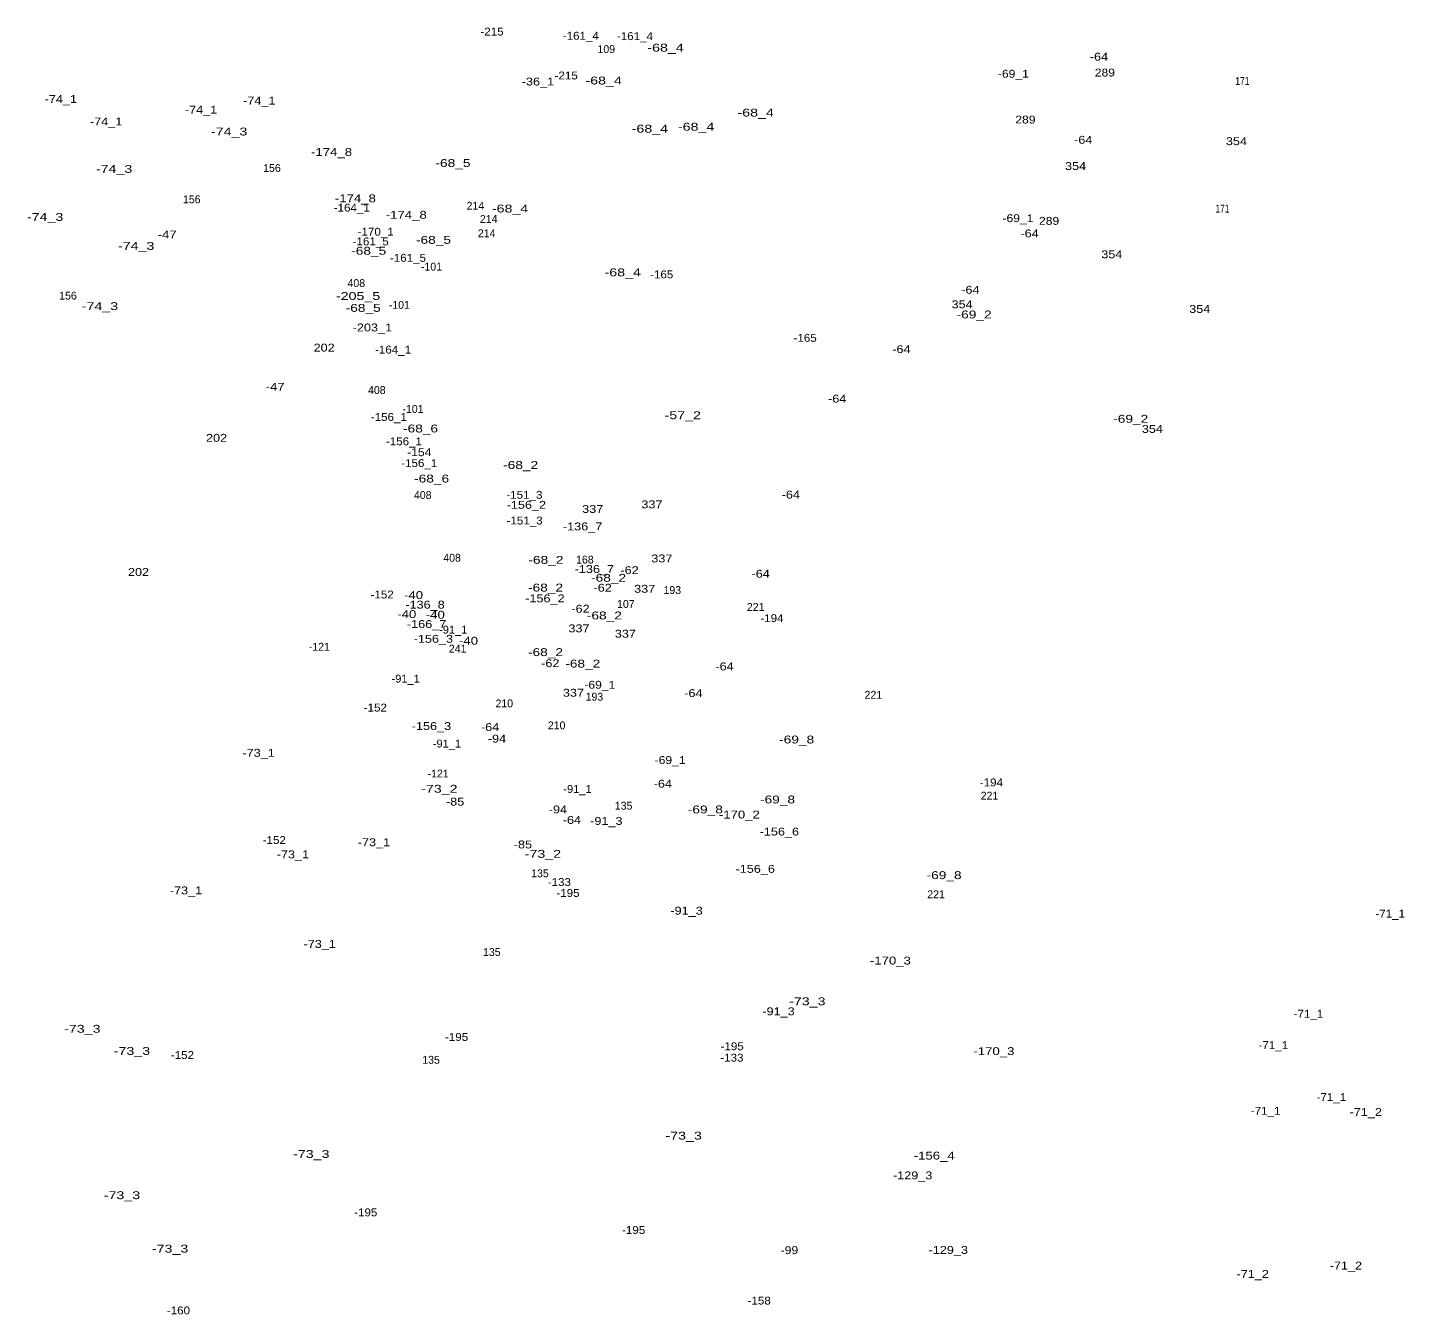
# Model space of a CAD drawing. Extents: x -658110 to -655750, y -1000429 to -997657.
# Drawn here: x -657635 to -656936, y -999768 to -999114 of the extents above; entities that cross this region are included whole.
import ezdxf
from ezdxf.enums import TextEntityAlignment as Align

# ---------------------------------------------------------------- set-up
doc = ezdxf.new("R2010")
doc.units = 0
doc.header["$LTSCALE"] = 1.6
doc.layers.add('24', color=7, linetype='Continuous')

msp = doc.modelspace()

# ---------------------------------------------------------------- texts
at = {"layer": '24'}
for s, width, p in [('-215', 1.1, (-657399.14, -999118.46)), ('-161_4', 1.1, (-657354.09, -999120.58)), ('-161_4', 1.1, (-657326.63, -999120.77)), ('-68_4', 1.35, (-657311.09, -999126.62)), ('-64', 1.2, (-657091.14, -999131.19)), ('-36_1', 1.2, (-657375.841, -999143.81)), ('-215', 1.1, (-657361.51, -999140.74)), ('-68_4', 1.35, (-657342.5, -999143.3)), ('-69_1', 1.15, (-657134.58, -999139.85)), ('289', 1.15, (-657088.14, -999139.25)), ('171', 0.8, (-657018.361, -999143.51)), ('-74_1', 1.2, (-657617.99, -999152.69)), ('-74_1', 1.2, (-657546.81, -999158.11)), ('-74_1', 1.2, (-657517.22, -999153.46)), ('-74_1', 1.2, (-657594.97, -999164.1)), ('-68_4', 1.35, (-657265.34, -999159.59)), ('289', 1.15, (-657128.46, -999163.1)), ('-74_3', 1.35, (-657532.54, -999169.18)), ('-68_4', 1.35, (-657319.04, -999167.73)), ('-68_4', 1.35, (-657295.58, -999166.76)), ('-174_8', 1.25, (-657480.59, -999179.55)), ('-64', 1.2, (-657099.111, -999173.38)), ('354', 1.2, (-657021.38, -999174.08)), ('-68_5', 1.3, (-657418.97, -999185.17)), ('354', 1.2, (-657103, -999186.68)), ('-74_3', 1.35, (-657590.949, -999188.14)), ('-174_8', 1.25, (-657468.49, -999203.08)), ('-74_3', 1.35, (-657625.949, -999212.52)), ('-164_1', 1.1, (-657470.32, -999207.82)), ('-174_8', 1.25, (-657442.67, -999211.44)), ('-68_4', 1.35, (-657389.99, -999208.26)), ('-69_1', 1.15, (-657132.25, -999213.16)), ('289', 1.15, (-657116.44, -999214.5)), ('171', 0.8, (-657028.451, -999208.29)), ('-47', 1.25, (-657564.01, -999221.45)), ('-170_1', 1.1, (-657458.191, -999220.03)), ('-64', 1.2, (-657126.351, -999220.89)), ('-74_3', 1.35, (-657579.73, -999227.22)), ('-161_5', 1.1, (-657460.721, -999224.93)), ('-68_5', 1.3, (-657428.86, -999224.16)), ('-68_5', 1.3, (-657461.72, -999229.69)), ('-161_5', 1.1, (-657441.801, -999233.28)), ('354', 1.2, (-657084.59, -999231.49)), ('-68_4', 1.35, (-657332.81, -999240.65)), ('-165', 1.1, (-657313.04, -999241.69)), ('-64', 1.2, (-657156.4, -999249.5)), ('-205_5', 1.35, (-657467.12, -999252.65)), ('-74_3', 1.35, (-657598.1, -999257.79)), ('-68_5', 1.3, (-657464.53, -999258.68)), ('354', 1.2, (-657160.569, -999256.88)), ('-69_2', 1.3, (-657154.51, -999262.02)), ('354', 1.2, (-657040, -999259.22)), ('-203_1', 1.2, (-657459.86, -999268.61)), ('-165', 1.1, (-657240.25, -999273.88)), ('202', 1.2, (-657484.34, -999278.85)), ('-164_1', 1.1, (-657449.36, -999279.86)), ('-64', 1.2, (-657191.39, -999279.65)), ('-47', 1.25, (-657509.201, -999298.72)), ('-64', 1.2, (-657223.961, -999304.76)), ('-156_1', 1.1, (-657451.51, -999314.05)), ('-57_2', 1.35, (-657302.37, -999313.15)), ('-69_2', 1.3, (-657075.02, -999314.97)), ('202', 1.2, (-657538.939, -999324.62)), ('-156_1', 1.1, (-657443.841, -999326.38)), ('-68_6', 1.3, (-657435.43, -999319.89)), ('354', 1.2, (-657064.04, -999320.12)), ('-154', 1.15, (-657436.07, -999331.92)), ('-156_1', 1.1, (-657436.081, -999337.45)), ('-68_2', 1.3, (-657384.64, -999338.41)), ('-68_6', 1.3, (-657429.81, -999345.3)), ('-151_3', 1.1, (-657382.709, -999353.54)), ('-64', 1.2, (-657247.52, -999353.44)), ('-156_2', 1.2, (-657381.731, -999358.63)), ('337', 1.2, (-657348.05, -999360.72)), ('337', 1.2, (-657318, -999358.39)), ('-151_3', 1.1, (-657382.62, -999366.6)), ('-136_7', 1.2, (-657353.18, -999369.59)), ('-68_2', 1.3, (-657371.8, -999386.56)), ('337', 1.2, (-657312.96, -999385.84)), ('202', 1.2, (-657578.54, -999392.7)), ('-136_7', 1.2, (-657347.23, -999391.2)), ('-68_2', 1.3, (-657340.01, -999395.66)), ('-62', 1.2, (-657329.34, -999391.78)), ('-64', 1.2, (-657262.831, -999393.59)), ('-68_2', 1.3, (-657372, -999400.62)), ('-62', 1.2, (-657343.01, -999400.7)), ('337', 1.2, (-657321.68, -999401.25)), ('-152', 1.1, (-657454.91, -999404.14)), ('-40', 1.25, (-657438.97, -999404.42)), ('-136_8', 1.2, (-657433.15, -999409.28)), ('-156_2', 1.2, (-657372.311, -999406.1)), ('-40', 1.25, (-657442.41, -999414.09)), ('-40', 1.25, (-657427.92, -999414.41)), ('-62', 1.2, (-657354.25, -999411.36)), ('-68_2', 1.3, (-657342.14, -999414.77)), ('-194', 1.1, (-657257.091, -999416.14)), ('-166_7', 1.2, (-657432.34, -999419.13)), ('-91_1', 1.05, (-657418.851, -999421.96)), ('337', 1.2, (-657355.03, -999421.32)), ('337', 1.2, (-657331.48, -999424.04)), ('-156_3', 1.2, (-657428.921, -999426.62)), ('-40', 1.25, (-657411.06, -999427.59)), ('-68_2', 1.3, (-657372, -999433.39)), ('-62', 1.2, (-657369.57, -999439)), ('-68_2', 1.3, (-657353.09, -999439.2)), ('-64', 1.2, (-657281.15, -999440.62)), ('-91_1', 1.05, (-657442.951, -999446.84)), ('-69_1', 1.15, (-657344.44, -999449.95)), ('337', 1.2, (-657357.84, -999454)), ('-64', 1.2, (-657296.951, -999454.19)), ('-152', 1.1, (-657458.37, -999461.52)), ('-156_3', 1.2, (-657429.89, -999470.9)), ('-64', 1.2, (-657400.12, -999471.41)), ('-91_1', 1.05, (-657422.02, -999479.78)), ('-94', 1.2, (-657396.62, -999477.29)), ('-69_8', 1.3, (-657244.56, -999477.72)), ('-73_1', 1.2, (-657517.61, -999484.48)), ('-69_1', 1.15, (-657308.77, -999488.16)), ('-64', 1.2, (-657312.461, -999500.16)), ('-194', 1.1, (-657145.731, -999499.5)), ('-73_2', 1.35, (-657425.88, -999502.73)), ('-91_1', 1.05, (-657355.791, -999502.83)), ('-69_8', 1.3, (-657254.26, -999508.16)), ('-85', 1.2, (-657417.88, -999509.27)), ('-94', 1.2, (-657365.711, -999513.21)), ('-69_8', 1.3, (-657290.9, -999513.21)), ('-64', 1.2, (-657358.63, -999518.54)), ('-91_3', 1.2, (-657341.13, -999519.06)), ('-170_2', 1.25, (-657273.64, -999515.81)), ('-152', 1.1, (-657509.64, -999528.74)), ('-156_6', 1.2, (-657253.35, -999524.44)), ('-73_1', 1.2, (-657500.22, -999536.01)), ('-73_1', 1.2, (-657459.06, -999529.86)), ('-85', 1.2, (-657383.47, -999530.99)), ('-73_2', 1.35, (-657373.32, -999535.75)), ('-133', 1.1, (-657364.99, -999550.06)), ('-156_6', 1.2, (-657265.58, -999543.37)), ('-69_8', 1.3, (-657169.73, -999546.56)), ('-73_1', 1.2, (-657554.45, -999554.3)), ('-195', 1.1, (-657360.59, -999555.6)), ('-91_3', 1.2, (-657300.421, -999564.58)), ('-71_1', 1.1, (-656943.341, -999566.09)), ('-73_1', 1.2, (-657486.59, -999581.45)), ('-170_3', 1.25, (-657196.981, -999589.91)), ('-73_3', 1.35, (-657239.15, -999610.58)), ('-91_3', 1.2, (-657253.76, -999615.67)), ('-71_1', 1.1, (-656984.831, -999616.9)), ('-73_3', 1.35, (-657607.06, -999624.53)), ('-195', 1.1, (-657417.14, -999628.68)), ('-195', 1.1, (-657277.27, -999633.39)), ('-71_1', 1.1, (-657002.671, -999632.81)), ('-73_3', 1.35, (-657581.89, -999635.76)), ('-152', 1.1, (-657556.28, -999637.85)), ('-133', 1.1, (-657277.431, -999639.19)), ('-170_3', 1.25, (-657144.441, -999635.87)), ('-71_1', 1.1, (-656973.201, -999659.18)), ('-71_1', 1.1, (-657006.551, -999666.16)), ('-71_2', 1.2, (-656955.75, -999666.74)), ('-73_3', 1.35, (-657301.89, -999678.76)), ('-73_3', 1.35, (-657490.88, -999688.06)), ('-156_4', 1.25, (-657174.74, -999688.9)), ('-129_3', 1.2, (-657185.681, -999698.92)), ('-73_3', 1.35, (-657586.93, -999708.98)), ('-195', 1.1, (-657463.23, -999717.7)), ('-195', 1.1, (-657327.28, -999726.64)), ('-73_3', 1.35, (-657562.53, -999736.1)), ('-99', 1.15, (-657248.22, -999736.88)), ('-129_3', 1.2, (-657167.63, -999736.76)), ('-71_2', 1.2, (-656965.83, -999744.7)), ('-71_2', 1.2, (-657013.14, -999748.97)), ('-158', 1.1, (-657263.571, -999762.47)), ('-160', 1.1, (-657558.28, -999767.45))]:
    msp.add_text(s, height=4, dxfattribs=dict(at, width=width)).set_placement(p, align=Align.CENTER)
for s, p in [('109', (-657341.16, -999127.36)), ('156', (-657510.821, -999187.69)), ('156', (-657551.53, -999203.59)), ('214', (-657407.6, -999206.84)), ('214', (-657400.819, -999213.53)), ('214', (-657401.88, -999220.81)), ('-101', (-657429.861, -999237.75)), ('408', (-657468.015, -999246.09)), ('156', (-657614.351, -999252.46)), ('-101', (-657446.181, -999257.15)), ('408', (-657457.605, -999300.39)), ('-101', (-657439.27, -999309.98)), ('408', (-657434.305, -999353.65)), ('408', (-657419.425, -999385.49)), ('168', (-657352.03, -999386.4)), ('193', (-657307.65, -999401.88)), ('107', (-657331.221, -999408.93)), ('221', (-657265.329, -999410.44)), ('-121', (-657486.791, -999430.66)), ('241', (-657416.61, -999431.62)), ('193', (-657347.201, -999455.99)), ('221', (-657205.62, -999455.04)), ('210', (-657392.92, -999459.4)), ('210', (-657366.36, -999470.55)), ('-121', (-657426.5, -999495)), ('221', (-657146.679, -999506.24)), ('135', (-657332.37, -999511.31)), ('135', (-657374.819, -999545.64)), ('221', (-657173.819, -999556.28)), ('135', (-657399.26, -999585.58)), ('135', (-657430.079, -999640.28))]:
    msp.add_text(s, height=4, dxfattribs=at).set_placement(p, align=Align.CENTER)

doc.saveas('drawing.dxf')
